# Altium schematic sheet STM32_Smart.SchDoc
size A3
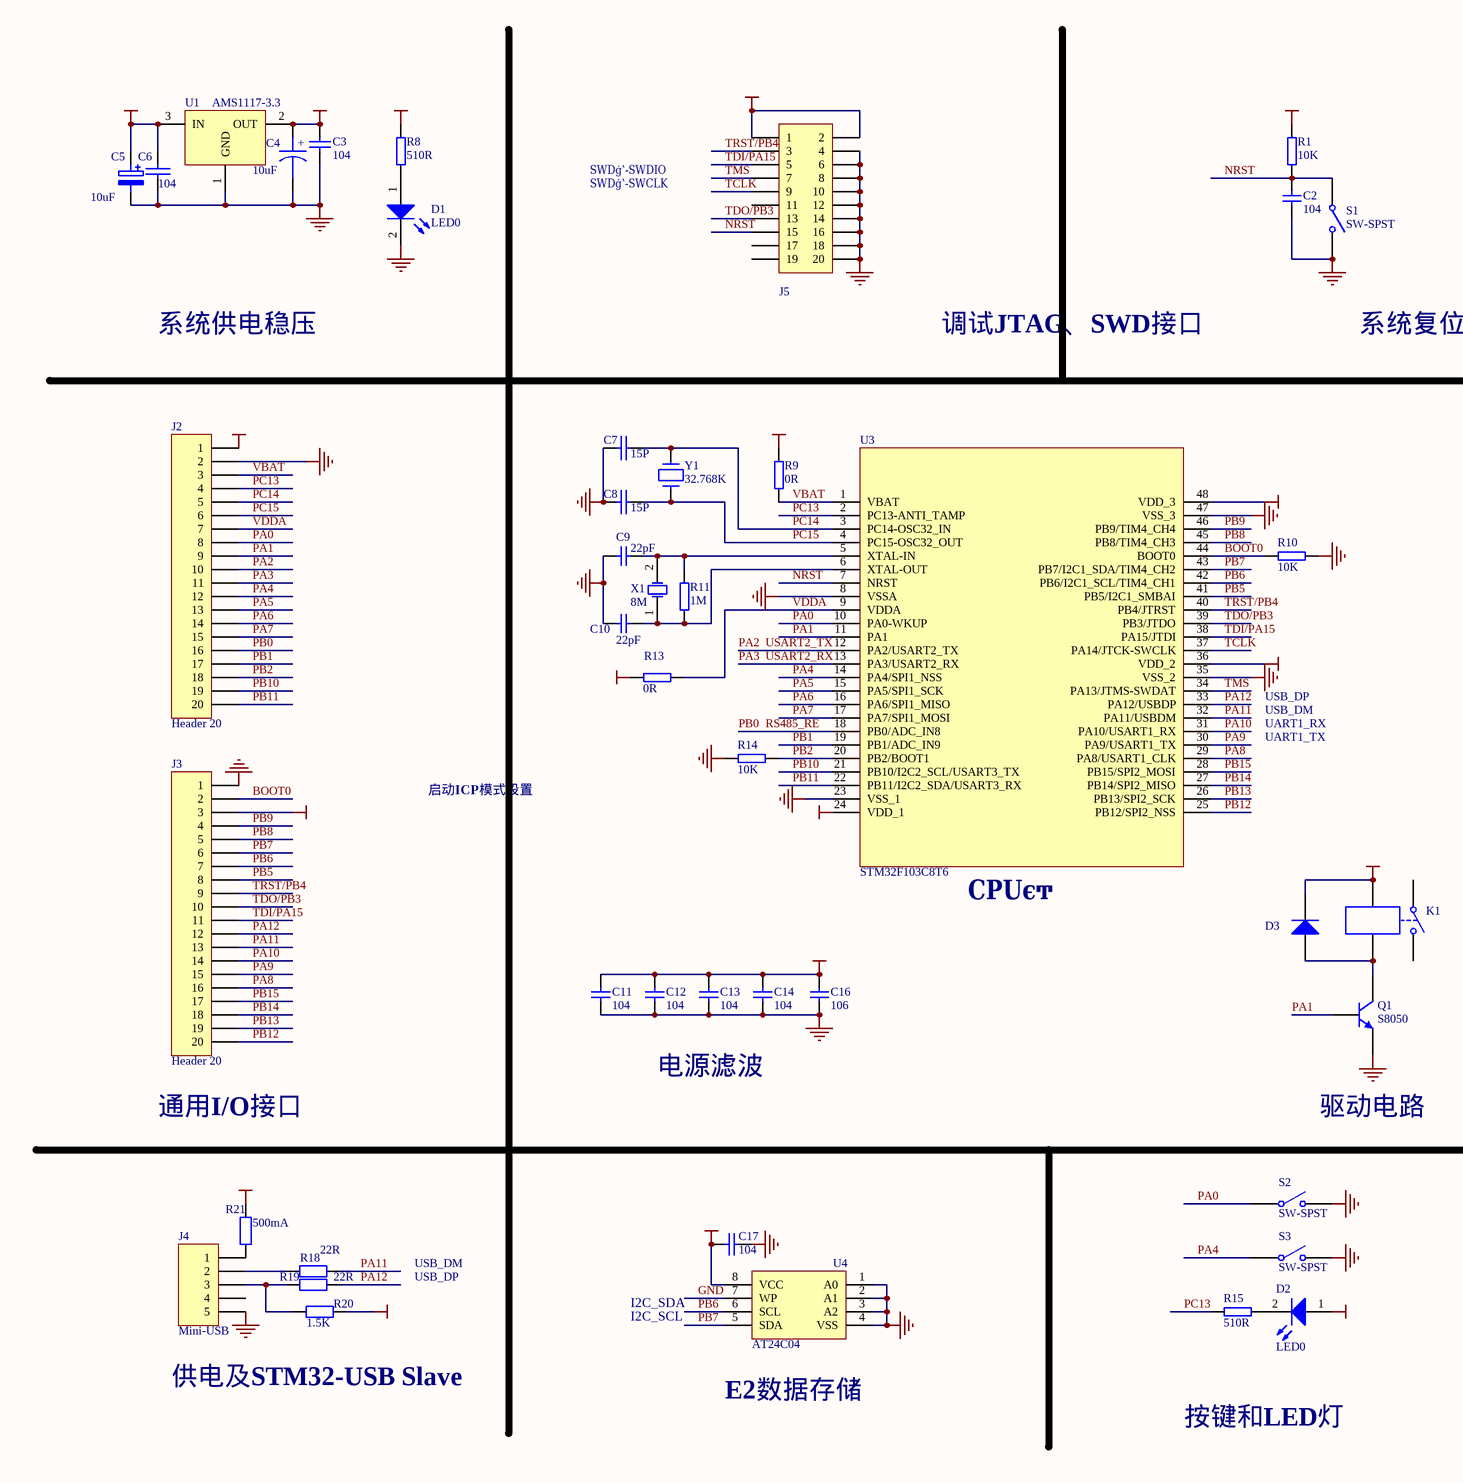
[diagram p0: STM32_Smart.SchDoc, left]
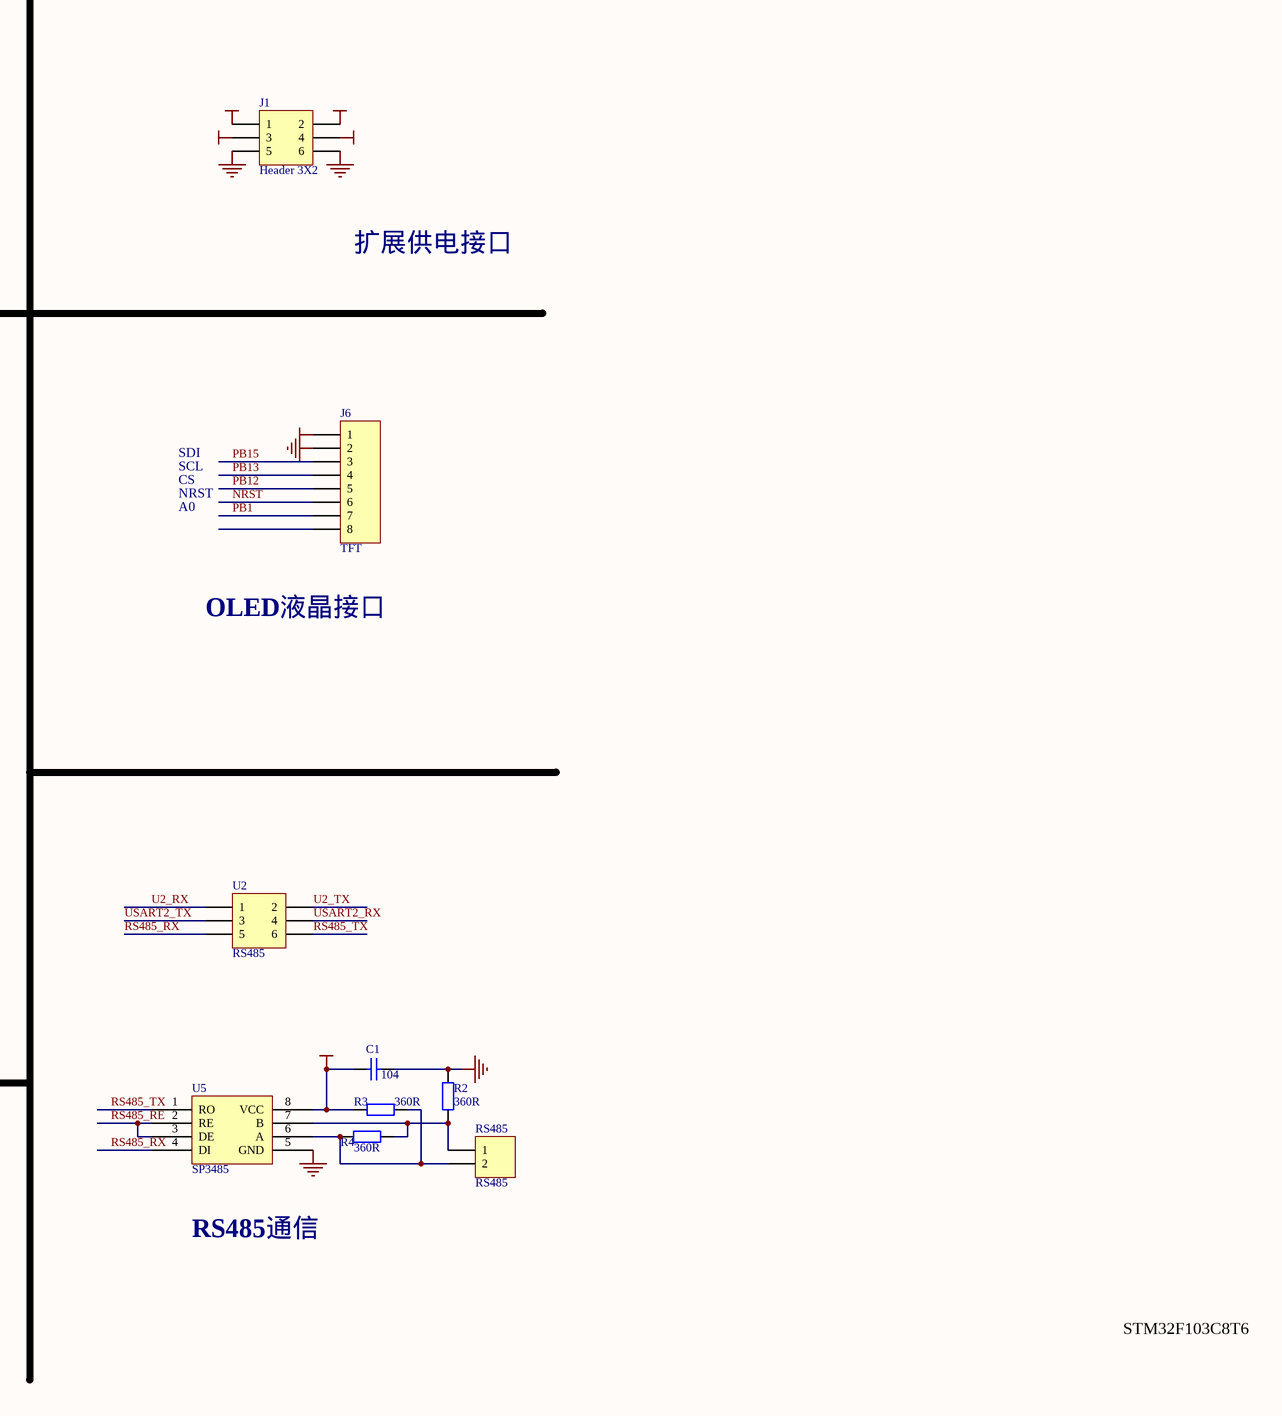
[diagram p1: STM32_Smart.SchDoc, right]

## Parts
C1  104  [RAD-0.3]
C2  104  [RC0603]
C3  104  [RC0603]
C4  10uF  [RC0805]
C5  10uF  [RC0805]
C6  104  [RC0603]
C7  15P  [RC0603]
C8  15P  [RC0603]
C9  22pF  [RC0603]
C10  22pF  [RC0603]
C11  104  [RC0603]
C12  104  [RC0603]
C13  104  [RC0603]
C14  104  [RC0603]
C16  106  [RC0805]
C17  104  [RC0603]
D1  LED0  [LED0805]
D2  LED0  [LED0805]
D3  Diode BAS21  [SO-G3/C2.5]  (value not drawn)
J1  Header 3X2  [IDE3X2-2.54]
J2  Header 20  [HDR1X20]
J3  Header 20  [HDR1X20]
J4  Mini-USB  [mini_USB]
J5  (no value)  [JTAG20P]
J6  TFT  [HDR1X8]
K1  Relay-SPST  [DIP-P4]  (value not drawn)
Q1  S8050  [BCY-W3]
R1  10K  [RC0603]
R2  360R  [AXIAL-0.4]
R3  360R  [AXIAL-0.4]
R4  360R  [AXIAL-0.4]
R8  510R  [RC0603]
R9  0R  [RC0603]
R10  10K  [RC0603]
R11  1M  [RC0603]
R13  0R  [RC0603]
R14  10K  [RC0603]
R15  510R  [RC0603]
R18  22R  [RC0603]
R19  22R  [RC0603]
R20  1.5K  [RC0603]
R21  500mA  [RC0805]
RS485  RS485  [HDR1X2H]
S1  SW-SPST  [SMT-KEY]
S2  SW-SPST  [SMT-KEY]
S3  SW-SPST  [SMT-KEY]
U1  AMS1117-3.3  [SOT223]
U2  RS485  [HDR2X3]
U3  STM32F103C8T6  [LQFP48]
U4  AT24C04  [SOIC-8P]
U5  SP3485
X1  8M  [SMD49S]
Y1  32.768K  [JZ32768]

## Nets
3V3: C1.1 C3.1 C4.1 C11.1 C12.1 C13.1 C14.1 C16.1 C17.2 D2.1(A) J1.3 J1.4 J2.1 J3.3 J5.1 J5.2 J6.1 R1.2 R3.1 R8.2 R9.2 R13.2 R20.1 U1.2(OUT) U3.24(VDD_1) U3.36(VDD_2) U3.48(VDD_3) U4.8(VCC) U5.8(VCC)
5V: C5.1 C6.1 D3.3(K) J1.1 J1.2 K1.3 R21.1 U1.3(IN)
GND: C1.2 C2.2 C3.2 C4.2 C5.2 C6.2 C7.1 C8.1 C9.2 C10.2 C11.2 C12.2 C13.2 C14.2 C16.2 C17.1 D1.2(K) J1.5 J1.6 J2.2 J3.1 J4.5 J5.4 J5.6 J5.8 J5.10 J5.12 J5.14 J5.16 J5.18 J5.20 J6.2 Q1.3(E) R2.2 R10.1 R14.2 S1.2(NO) S2.2(NO) S3.2(NO) U1.1(GND) U3.8(VSSA) U3.23(VSS_1) U3.35(VSS_2) U3.47(VSS_3) U4.1(A0) U4.2(A1) U4.3(A2) U4.4(VSS) U4.7(WP) U5.5(GND)
BOOT0: J3.2 R10.2 U3.44(BOOT0)
NRST: C2.1 J5.15 J6.6 R1.1 S1.1(COMMON) U3.7(NRST)
PA0: J2.8 S2.1(COMMON) U3.10(PA0-WKUP)
PA1: J2.9 Q1.2(B) U3.11(PA1)
PA2: J2.10 U2.3 U3.12(PA2/USART2_TX)  [also labelled USART2_TX]
PA3: J2.11 U2.4 U3.13(PA3/USART2_RX)  [also labelled USART2_RX]
PA4: J2.12 S3.1(COMMON) U3.14(PA4/SPI1_NSS)
PA5: J2.13 U3.15(PA5/SPI1_SCK)
PA6: J2.14 U3.16(PA6/SPI1_MISO)
PA7: J2.15 U3.17(PA7/SPI1_MOSI)
PA8: J3.16 U3.29(PA8/USART1_CLK)
PA9: J3.15 U3.30(PA9/USART1_TX)
PA10: J3.14 U3.31(PA10/USART1_RX)
PA11: J3.13 R18.1 U3.32(PA11/USBDM)
PA12: J3.12 R19.1 U3.33(PA12/USBDP)
PB0: J2.16 U3.18(PB0/ADC_IN8) U5.2(RE) U5.3(DE)  [also labelled RS485_RE]
PB1: J2.17 J6.7 U3.19(PB1/ADC_IN9)
PB2: J2.18 R14.1 U3.20(PB2/BOOT1)
PB5: J3.8 U3.41(PB5/I2C1_SMBAI)
PB6: J3.7 U3.42(PB6/I2C1_SCL/TIM4_CH1) U4.6(SCL)
PB7: J3.6 U3.43(PB7/I2C1_SDA/TIM4_CH2) U4.5(SDA)
PB8: J3.5 U3.45(PB8/TIM4_CH3)
PB9: J3.4 U3.46(PB9/TIM4_CH4)
PB10: J2.19 U3.21(PB10/I2C2_SCL/USART3_TX)
PB11: J2.20 U3.22(PB11/I2C2_SDA/USART3_RX)
PB12: J3.20 J6.5 U3.25(PB12/SPI2_NSS)
PB13: J3.19 J6.4 U3.26(PB13/SPI2_SCK)
PB14: J3.18 U3.27(PB14/SPI2_MISO)
PB15: J3.17 J6.3 U3.28(PB15/SPI2_MOSI)
PC13: J2.4 R15.1 U3.2(PC13-ANTI_TAMP)
PC14: C7.2 J2.5 U3.3(PC14-OSC32_IN) Y1.2
PC15: C8.2 J2.6 U3.4(PC15-OSC32_OUT) Y1.1
RS485_RX: U2.5 U5.4(DI)
RS485_TX: U2.6 U5.1(RO)
TCLK: J5.9 U3.37(PA14/JTCK-SWCLK)
TDI/PA15: J3.11 J5.5 U3.38(PA15/JTDI)
TDO/PB3: J3.10 J5.13 U3.39(PB3/JTDO)
TMS: J5.7 U3.34(PA13/JTMS-SWDAT)
TRST/PB4: J3.9 J5.3 U3.40(PB4/JTRST)
U2_RX: U2.1
U2_TX: U2.2
VBAT: J2.3 R9.1 U3.1(VBAT)
VDDA: J2.7 R13.1 U3.9(VDDA)
NetC9_1: C9.1 R11.2 U3.5(XTAL-IN) X1.2
NetC10_1: C10.1 R11.1 U3.6(XTAL-OUT) X1.1
NetD1_1: D1.1(A) R8.1
NetD2_2: D2.2(K) R15.2
NetD3_1: D3.1(A) K1.4 Q1.1(C)
NetJ4_1: J4.1 R21.2
NetJ4_2: J4.2 R18.2
NetJ4_3: J4.3 R19.2 R20.2
NetR2_1: R2.1 R4.2 RS485.1 U5.7(B)
NetR3_2: R3.2 R4.1 RS485.2 U5.6(A)

Not connected (* = marked no-connect by the designer): J4 4; J5 11 17 19; J6 8; K1 1 2

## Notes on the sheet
- SWDģʽ-SWCLK
- SWDģʽ-SWDIO
- 系统供电稳压
- (near J5) 调试JTAG、SWD接口
- 系统复位
- 扩展供电接口
- SDI
- SCL
- CS
- NRST
- A0
- USB_DP
- OLED液晶接口
- UART1_TX
- UART1_RX
- USB_DM
- 启动ICP模式设置
- CPUϵͳ
- 电源滤波
- (near J3) 通用I/O接口
- 驱动电路
- I2C_SDA
- RS485通信
- I2C_SCL
- 供电及STM32-USB Slave
- (near U4) E2数据存储
- 按键和LED灯
- STM32F103C8T6

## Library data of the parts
C1 C3 C17 = Cap: Capacitor
C2 C11-C14 C16 = CAP1: Capacitor; Tolerate: 50V; Value: 100nF; TOL: 10%; ERP: 0103020075; PCB_Layout: Top Layer SMC
C4 = CAPACITOR POL: Capacitor
C5 = ELECTRO2
C6 = CAP: Capacitor
C7 C8 = CAP
C9 C10 = CAP1: Capacitor; Tolerate: 50V; Value: 20pF; TOL: 2%; ERP: 0103020090; PCB_Layout: Top Layer SMC
D1 D2 = LED0: Typical INFRARED GaAs LED
D3 = Diode BAS21: Silicon Switching Diode for High-Speed, High-Voltage Switching; Note: Pin 2 is not connected and not drawn.
J1 U2 = Header 3X2: Header, 3-Pin, Dual row
J2 J3 = Header 20: Header, 20-Pin
J4 = Header 5: Header, 5-Pin
J5 = Header 10X2H: Header, 10-Pin, Dual row, Right Angle
J6 = Header 8: Header, 8-Pin
K1 = Relay-SPST: Single-Pole Single-Throw Relay
Q1 = NPN: NPN Bipolar Transistor
R1 R8-R11 R13-R15 = R
R2-R4 R18-R21 = Res2: Resistor
RS485 = Header 2H: Header, 2-Pin, Right Angle
S1-S3 = SW-SPST: Single-Pole, Single-Throw Switch
U1 = LT1085CM-3.3
U4 = EPROM
U5 = Component_1
X1 = XTAL_SMD: Crystal Oscillator; ERP: 0103040021; Value: 8MHz; TOL: ±20ppm; Tolerate: ROSON -20_+70 20pf; PCB_Layout: Top Layer SMC
Y1 = CRYSTAL: 晶振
